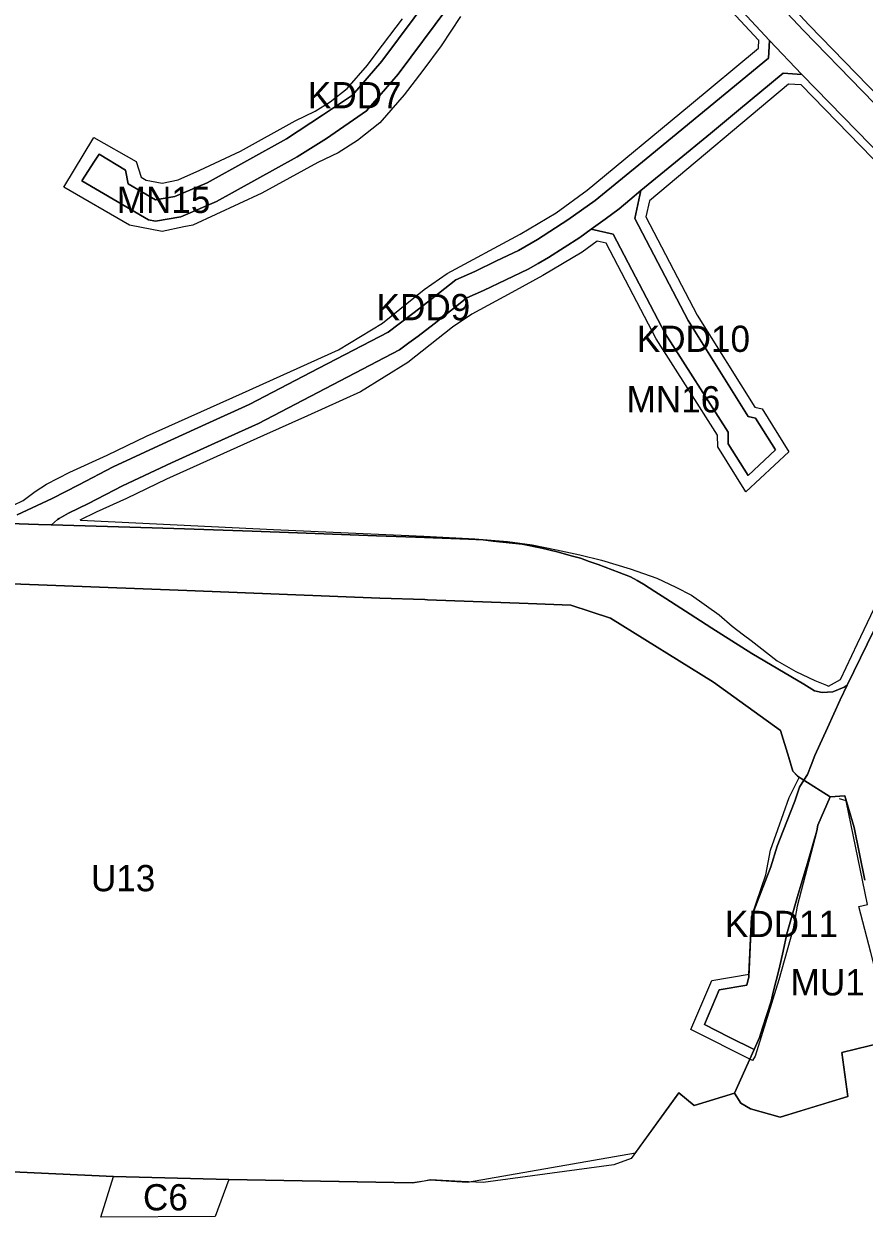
# Model space of a CAD drawing. Extents: x 7428841 to 7433518, y 5545054 to 5546840.
# Drawn here: x 7429933 to 7430252.9, y 5545095 to 5545549.4 of the extents above; entities that cross this region are included whole.
import ezdxf

# ---------------------------------------------------------------- set-up
doc = ezdxf.new("R2010")
doc.units = 0
for name, color, linetype in [('linie_rozgraniczajace', 7, 'Continuous'), ('linie_zabudowy_nieprzekraczalne', 7, 'Continuous'), ('oznaczenia_przeznaczen', 7, 'Continuous')]:
    doc.layers.add(name, color=color, linetype=linetype)

msp = doc.modelspace()

# ---------------------------------------------------------------- linework, layer by layer
at = {"layer": 'linie_rozgraniczajace'}
for points in [[(7430325.58, 5545455.53), (7430312.26, 5545461.16), (7430308.65, 5545461.94), (7430303.75, 5545463), (7430294.58, 5545464.99), (7430289.44, 5545468.09), (7430288.37, 5545469.23), (7430255.3, 5545503.38), (7430229.22, 5545530.19), (7430216.84, 5545543.13), (7430184.02, 5545578.55), (7430149.29, 5545617.28), (7430139.47, 5545621.59), (7430134.46, 5545628.43), (7430133.95, 5545633.65), (7430133.85, 5545634.69), (7430133.44, 5545638.87)], [(7430184.02, 5545578.55), (7430216.84, 5545543.13), (7430216.46, 5545536.4), (7430199.99, 5545522.75), (7430169.9, 5545497.98), (7430150.54, 5545482.12), (7430140.13, 5545474.77), (7430128.5, 5545467.28), (7430121.25, 5545463.06), (7430112.94, 5545459.12), (7430104.62, 5545455.18), (7430097.41, 5545451.95), (7430084.26, 5545441.55), (7430071.73, 5545432.06), (7430045.23, 5545418.26), (7430018.74, 5545404.46), (7430002.3, 5545396.99), (7429985.87, 5545389.51), (7429966.95, 5545380.68), (7429953.87, 5545373.84), (7429943.77, 5545368.69), (7429930.43, 5545362.4)], [(7430211.33, 5545566.73), (7430229.77, 5545546.84), (7430297.16, 5545477.57), (7430299.21, 5545476.27), (7430307.56, 5545474.46), (7430315.9, 5545472.65), (7430319.7, 5545471.04), (7430324.69, 5545468.93), (7430333.47, 5545465.22), (7430342.31, 5545463.53), (7430333.84, 5545457.18), (7430326.2, 5545448.73), (7430325.96, 5545448.44), (7430325.58, 5545455.53)], [(7430359.72, 5545551.27), (7430356.4, 5545538.02), (7430356.1, 5545526.65), (7430336.95, 5545508.06), (7430322.25, 5545491.26), (7430307.56, 5545474.46), (7430299.21, 5545476.27), (7430297.16, 5545477.57), (7430229.77, 5545546.84), (7430211.33, 5545566.73)], [(7430087.86, 5545560.33), (7430069.26, 5545535.23), (7430058.09, 5545522.28), (7430046.7, 5545514.62), (7430032.91, 5545505.64), (7430002.79, 5545488.95), (7429990.43, 5545483.71), (7429983.16, 5545482.4), (7429972.73, 5545488.45), (7429971.67, 5545493.69), (7429961.63, 5545499.76), (7429959.88, 5545497.11), (7429955, 5545489.66), (7429980.42, 5545474.74), (7429983.13, 5545474.27), (7429992.73, 5545476), (7430006.3, 5545481.75), (7430036.98, 5545498.75), (7430048.19, 5545505.79), (7430063.47, 5545516.26), (7430075.51, 5545530.23), (7430094.37, 5545555.69)], [(7430094.37, 5545555.69), (7430075.51, 5545530.23), (7430063.47, 5545516.26), (7430048.19, 5545505.79), (7430036.98, 5545498.75), (7430006.3, 5545481.75), (7429992.73, 5545476), (7429983.13, 5545474.27), (7429980.42, 5545474.74), (7429955, 5545489.66), (7429959.88, 5545497.11), (7429961.63, 5545499.76), (7429971.67, 5545493.69), (7429972.73, 5545488.45), (7429983.16, 5545482.4), (7429990.43, 5545483.71), (7430002.79, 5545488.95), (7430032.91, 5545505.64), (7430046.7, 5545514.62), (7430058.09, 5545522.28), (7430069.26, 5545535.23), (7430087.86, 5545560.33)], [(7429930.43, 5545362.4), (7429943.77, 5545368.69), (7429953.87, 5545373.84), (7429966.95, 5545380.68), (7429985.87, 5545389.51), (7430002.3, 5545396.99), (7430018.74, 5545404.46), (7430045.23, 5545418.26), (7430071.73, 5545432.06), (7430084.26, 5545441.55), (7430097.41, 5545451.95), (7430104.62, 5545455.18), (7430112.94, 5545459.12), (7430121.25, 5545463.06), (7430128.5, 5545467.28), (7430140.13, 5545474.77), (7430150.54, 5545482.12), (7430169.9, 5545497.98), (7430199.99, 5545522.75), (7430216.46, 5545536.4), (7430216.84, 5545543.13), (7430229.22, 5545530.19), (7430222.06, 5545530.65), (7430205.1, 5545516.59), (7430194.35, 5545507.67), (7430181.1, 5545496.81), (7430167.84, 5545485.95), (7430163.72, 5545482.45), (7430159.6, 5545478.95), (7430154.31, 5545475.11), (7430148.92, 5545471.28), (7430144.6, 5545468.13), (7430138.65, 5545464.3), (7430132.69, 5545460.46), (7430128.84, 5545458.22), (7430124.99, 5545455.97), (7430116.48, 5545451.94), (7430107.97, 5545447.92), (7430101.6, 5545445.06), (7430089.2, 5545435.25), (7430083.16, 5545430.54), (7430079.57, 5545427.9), (7430075.97, 5545425.25), (7430022.25, 5545397.27), (7430005.73, 5545389.76), (7429989.22, 5545382.25), (7429970.5, 5545373.51), (7429957.58, 5545366.76), (7429950.04, 5545363.1), (7429946.36, 5545361.08), (7429945.75, 5545360.72), (7429943.55, 5545358.65), (7429943.43, 5545358.65), (7429938.58, 5545358.8), (7429934.73, 5545358.92), (7429920.54, 5545359.36)], [(7430259.11, 5545323.6), (7430246.49, 5545297.57), (7430245.24, 5545296.79), (7430240.91, 5545295.09), (7430236.92, 5545294.77), (7430234, 5545295.48), (7430229.89, 5545297.92), (7430210.16, 5545309.58), (7430202.52, 5545314.44), (7430194.88, 5545319.3), (7430190.6, 5545322.12), (7430177.38, 5545330.58), (7430173.16, 5545333.28), (7430168.95, 5545335.98), (7430166.42, 5545337.42), (7430163.89, 5545338.86), (7430159.63, 5545340.5), (7430151.64, 5545343.53), (7430148.25, 5545344.71), (7430144.86, 5545345.9), (7430141.9, 5545346.72), (7430135.97, 5545348.36), (7430130.17, 5545349.74), (7430122.72, 5545351.23), (7430111.67, 5545352.45), (7430107.83, 5545352.89), (7430102.29, 5545353.23), (7430082.11, 5545353.89), (7430067.3, 5545354.42), (7430037.17, 5545355.64), (7430019.94, 5545356.23), (7429994.1, 5545357.1), (7429981.85, 5545357.5), (7429943.56, 5545358.65), (7429943.55, 5545358.65), (7429945.75, 5545360.72), (7429946.36, 5545361.08), (7429950.04, 5545363.1), (7429957.58, 5545366.76), (7429970.5, 5545373.51), (7429989.22, 5545382.25), (7430005.73, 5545389.76), (7430022.25, 5545397.27), (7430075.97, 5545425.25), (7430079.57, 5545427.9), (7430083.16, 5545430.54), (7430089.2, 5545435.25), (7430101.6, 5545445.06), (7430107.97, 5545447.92), (7430116.48, 5545451.94), (7430124.99, 5545455.97), (7430128.84, 5545458.22), (7430132.69, 5545460.46), (7430138.65, 5545464.3), (7430144.6, 5545468.13), (7430148.92, 5545471.28), (7430157.39, 5545469.39), (7430177.2, 5545431.51), (7430201.09, 5545393.98), (7430201.12, 5545389.51), (7430208.69, 5545377.42), (7430219.12, 5545387.15), (7430211.55, 5545399.24), (7430208.8, 5545399.87), (7430197.34, 5545418.18), (7430185.88, 5545436.49), (7430175.72, 5545455.91), (7430165.56, 5545475.34), (7430167.84, 5545485.95), (7430181.1, 5545496.81), (7430194.35, 5545507.67), (7430205.1, 5545516.59), (7430222.06, 5545530.65), (7430229.22, 5545530.19), (7430255.3, 5545503.38)], [(7429920.54, 5545359.36), (7429934.73, 5545358.92), (7429938.58, 5545358.8), (7429943.43, 5545358.65), (7429943.55, 5545358.65), (7429943.56, 5545358.65), (7429981.85, 5545357.5), (7429994.1, 5545357.1), (7430019.94, 5545356.23), (7430037.17, 5545355.64), (7430067.3, 5545354.42), (7430082.11, 5545353.89), (7430102.29, 5545353.23), (7430107.83, 5545352.89), (7430111.67, 5545352.45), (7430122.72, 5545351.23), (7430130.17, 5545349.74), (7430135.97, 5545348.36), (7430141.9, 5545346.72), (7430144.86, 5545345.9), (7430148.25, 5545344.71), (7430151.64, 5545343.53), (7430159.63, 5545340.5), (7430163.89, 5545338.86), (7430166.42, 5545337.42), (7430168.95, 5545335.98), (7430173.16, 5545333.28), (7430177.38, 5545330.58), (7430190.6, 5545322.12), (7430194.88, 5545319.3), (7430202.52, 5545314.44), (7430210.16, 5545309.58), (7430229.89, 5545297.92), (7430234, 5545295.48), (7430236.92, 5545294.77), (7430240.91, 5545295.09), (7430245.24, 5545296.79), (7430246.49, 5545297.57), (7430243.74, 5545291.97), (7430238.96, 5545281.36), (7430234.18, 5545270.75), (7430232.78, 5545267.15), (7430231.38, 5545263.55), (7430229.95, 5545261.35), (7430227.5, 5545262.9), (7430225.75, 5545264.88), (7430224.18, 5545270.02), (7430221.04, 5545280.34), (7430195.57, 5545298.71), (7430156.29, 5545323.05), (7430141.2, 5545328.03), (7430125.01, 5545328.63), (7430086.64, 5545330.07), (7430085.61, 5545330.21), (7430068.54, 5545330.76), (7429994.98, 5545333.61), (7429895.15, 5545337.47)], [(7429895.15, 5545337.47), (7429994.98, 5545333.61), (7430068.54, 5545330.76), (7430085.61, 5545330.21), (7430086.64, 5545330.07), (7430125.01, 5545328.63), (7430141.2, 5545328.03), (7430156.29, 5545323.05), (7430195.57, 5545298.71), (7430221.04, 5545280.34), (7430224.18, 5545270.02), (7430225.75, 5545264.88), (7430227.5, 5545262.9), (7430229.95, 5545261.35), (7430228.24, 5545258.76), (7430226.53, 5545253.44), (7430222, 5545242.06), (7430219.75, 5545236.25), (7430217.38, 5545228.33), (7430213.66, 5545218.87), (7430209.95, 5545209.41), (7430208.98, 5545186.56), (7430208.22, 5545183.3), (7430197.73, 5545181.56), (7430192.1, 5545168.35), (7430201.55, 5545163.56), (7430211, 5545158.77), (7430203.58, 5545142.22), (7430188.19, 5545137.46), (7430182.29, 5545142.3), (7430164.23, 5545117.25), (7430157.56, 5545114.91), (7430107.8, 5545108.22), (7430099.49, 5545108.6), (7430087.61, 5545109.15), (7430085.34, 5545108.71), (7430080.94, 5545108.08), (7430010.97, 5545109.36), (7429967.17, 5545110.46), (7429766.71, 5545119.71)], [(7430229.95, 5545261.35), (7430231.38, 5545263.55), (7430232.78, 5545267.15), (7430234.18, 5545270.75), (7430238.96, 5545281.36), (7430243.74, 5545291.97), (7430246.49, 5545297.57), (7430259.11, 5545323.6)], [(7430253.11, 5545223.25), (7430249.09, 5545243.33), (7430245.53, 5545255.38), (7430239.96, 5545255.05), (7430229.95, 5545261.35)], [(7430265.18, 5545162.82), (7430244.43, 5545157.62), (7430246.62, 5545140.9), (7430231.3, 5545136.26), (7430220.88, 5545133.1), (7430209.63, 5545136.23), (7430205.95, 5545138.43), (7430203.58, 5545142.22), (7430211, 5545158.77), (7430213.05, 5545163.41), (7430214.23, 5545167.13), (7430217.44, 5545177.23), (7430218.31, 5545180.69), (7430220.54, 5545189.49), (7430222.01, 5545196.28), (7430223.46, 5545202.91), (7430227.51, 5545217.15), (7430231.52, 5545230.7), (7430234.92, 5545242.1), (7430235.21, 5545244.29), (7430239.96, 5545255.05), (7430245.53, 5545255.38), (7430249.09, 5545243.33), (7430253.11, 5545223.25)]]:
    msp.add_lwpolyline(points, dxfattribs=at)
for points in [[(7430148.92, 5545471.28), (7430154.31, 5545475.11), (7430159.6, 5545478.95), (7430163.72, 5545482.45), (7430167.84, 5545485.95), (7430165.56, 5545475.34), (7430175.72, 5545455.91), (7430185.88, 5545436.49), (7430197.34, 5545418.18), (7430208.8, 5545399.87), (7430211.55, 5545399.24), (7430219.12, 5545387.15), (7430208.69, 5545377.42), (7430201.12, 5545389.51), (7430201.09, 5545393.98), (7430177.2, 5545431.51), (7430157.39, 5545469.39)], [(7430192.1, 5545168.35), (7430197.73, 5545181.56), (7430208.22, 5545183.3), (7430208.98, 5545186.56), (7430209.95, 5545209.41), (7430213.66, 5545218.87), (7430217.38, 5545228.33), (7430219.75, 5545236.25), (7430222, 5545242.06), (7430226.53, 5545253.44), (7430228.24, 5545258.76), (7430229.95, 5545261.35), (7430239.96, 5545255.05), (7430235.21, 5545244.29), (7430234.92, 5545242.1), (7430231.52, 5545230.7), (7430227.51, 5545217.15), (7430223.46, 5545202.91), (7430222.01, 5545196.28), (7430220.54, 5545189.49), (7430218.31, 5545180.69), (7430217.44, 5545177.23), (7430214.23, 5545167.13), (7430213.05, 5545163.41), (7430211, 5545158.77), (7430201.55, 5545163.56)], [(7429962.33, 5545094.98), (7429967.17, 5545110.46), (7430010.97, 5545109.36), (7430005.8, 5545095.25)]]:
    msp.add_lwpolyline(points, close=True, dxfattribs=at)
at = {"layer": 'linie_zabudowy_nieprzekraczalne'}
for points in [[(7430167.85, 5545631.23), (7430162.47, 5545626.69), (7430161.79, 5545625.86), (7430166.3, 5545621), (7430195.12, 5545588.64), (7430231.95, 5545548.9), (7430299.06, 5545479.91), (7430300.36, 5545479.08), (7430309.83, 5545477.03)], [(7430212.69, 5545543.2), (7430181.8, 5545576.54), (7430167.38, 5545592.73), (7430147.49, 5545614.79), (7430141.98, 5545616.32)], [(7430099.17, 5545552.22), (7430091.9, 5545541.01), (7430084.85, 5545531.7), (7430077.8, 5545522.39), (7430068.56, 5545511.69), (7430059.97, 5545504.98), (7430052.62, 5545500.34), (7430044.88, 5545496.68), (7430023.55, 5545484.91), (7429997.37, 5545472.74), (7429993.88, 5545472.14), (7429985.64, 5545470.4), (7429973.19, 5545472.8), (7429948.18, 5545487.21), (7429959.57, 5545506.12), (7429975.76, 5545496.99), (7429977.59, 5545491.06), (7429979.58, 5545489.9), (7429985.58, 5545488.74), (7429991.74, 5545489.97), (7429999.97, 5545493.72), (7430015.4, 5545500.97), (7430036.24, 5545512.46), (7430043.93, 5545516.14), (7430049.6, 5545519.72), (7430056.09, 5545524.79), (7430063.8, 5545533.72), (7430067.07, 5545538.1), (7430077.15, 5545551.35)], [(7429916.68, 5545362.36), (7429928.99, 5545366.14), (7429932.75, 5545367.92), (7429937.28, 5545371.39), (7429941.65, 5545374.15), (7429950.43, 5545378.73), (7429964.76, 5545385.17), (7429979.65, 5545392.39), (7430016.19, 5545408.83), (7430052.74, 5545425.27), (7430069.56, 5545435.44), (7430085.37, 5545448.31), (7430094.13, 5545454.32), (7430121.89, 5545469.39), (7430135.65, 5545477.49), (7430147.49, 5545486.06), (7430186.38, 5545518.29), (7430212.67, 5545540.14), (7430212.85, 5545543.36)], [(7430228.97, 5545526.2), (7430224.11, 5545526.47), (7430171.13, 5545482.01)], [(7430301.8, 5545460.36), (7430293.42, 5545462.17), (7430287.64, 5545465.84), (7430228.94, 5545526.18)], [(7430171.13, 5545482.01), (7430169.77, 5545475.91), (7430189.36, 5545438.48), (7430211.31, 5545403.4), (7430214.06, 5545402.77), (7430224.26, 5545386.48), (7430207.87, 5545371.19), (7430197.13, 5545388.35), (7430197.1, 5545392.79), (7430185.78, 5545410.59), (7430173.74, 5545429.5), (7430154.7, 5545465.89), (7430151.3, 5545466.7)], [(7430151.3, 5545466.7), (7430145.55, 5545462.43), (7430130.62, 5545453.58), (7430118.8, 5545447.1), (7430103.51, 5545438.93), (7430096.16, 5545433.89), (7430079.15, 5545420.42), (7430061.19, 5545409.34), (7430040.96, 5545400.19), (7430024.21, 5545392.7), (7429987.24, 5545376.07), (7429972.03, 5545368.71), (7429960.46, 5545363.41), (7429954.35, 5545360.46)], [(7430239.29, 5545297.24), (7430239.29, 5545297.24), (7430243.9, 5545299.69), (7430243.9, 5545299.69), (7430250.35, 5545313.39), (7430268.09, 5545350.71), (7430276.26, 5545368.76), (7430282.12, 5545380.85), (7430286.65, 5545388.92), (7430295.47, 5545407.3), (7430298.99, 5545413.85), (7430303.59, 5545421.71), (7430312.81, 5545436.57), (7430319.95, 5545446.16), (7430323.12, 5545449.81)], [(7429954.49, 5545360.44), (7429967.69, 5545359.81), (7430028.08, 5545356.84), (7430056.41, 5545355.58), (7430085.27, 5545354.26), (7430104.67, 5545353.3), (7430117.08, 5545352.28), (7430126.53, 5545351.02), (7430135.72, 5545349.14), (7430144.64, 5545347.21), (7430152.95, 5545345.13), (7430163.79, 5545341.83), (7430173.91, 5545338.3), (7430181.14, 5545334.91), (7430187.2, 5545331.91), (7430197.7, 5545324.38), (7430202.66, 5545320.06), (7430206.9, 5545316.75), (7430209.89, 5545314.59), (7430219.77, 5545306.89), (7430226.91, 5545302.73), (7430234.13, 5545299.38), (7430238.53, 5545297.54), (7430239.3, 5545297.25)], [(7430141.2, 5545328.03), (7430125.01, 5545328.63), (7430068.54, 5545330.76), (7429994.98, 5545333.61), (7429945.06, 5545335.54), (7429895.15, 5545337.47), (7429871.81, 5545338.38), (7429854.74, 5545339.04), (7429803.03, 5545340.9), (7429751.31, 5545342.75), (7429741.75, 5545333.86), (7429738.51, 5545297), (7429735.28, 5545260.15), (7429733.04, 5545234.55), (7429730.55, 5545206.18)], [(7430195.57, 5545298.71), (7430156.29, 5545323.05), (7430141.2, 5545328.03)], [(7430221.04, 5545280.34), (7430195.57, 5545298.71)], [(7430209.02, 5545187.51), (7430209.95, 5545209.41), (7430215.42, 5545225.36), (7430217.18, 5545234.76), (7430219.97, 5545242.65), (7430224.31, 5545254.78), (7430228.19, 5545262.42), (7430225.75, 5545264.88), (7430223.4, 5545272.61), (7430221.04, 5545280.34)], [(7430245.53, 5545255.37), (7430239.96, 5545255.05), (7430239.96, 5545255.05), (7430237.58, 5545249.65), (7430235.21, 5545244.29), (7430234.92, 5545242.1), (7430227.43, 5545213.38), (7430225.85, 5545204.78), (7430220.46, 5545185.39), (7430211.4, 5545156.25), (7430210.39, 5545154.59)], [(7430263.89, 5545162.52), (7430255.48, 5545195.72), (7430250.93, 5545213.22), (7430254.2, 5545214.02), (7430246.03, 5545253.5), (7430243.52, 5545254.3)], [(7429730.55, 5545206.18), (7429727.14, 5545167.45), (7429732.75, 5545160.67), (7429731.08, 5545153.27), (7429744.53, 5545151.94), (7429742.07, 5545126.13), (7429766.71, 5545119.71), (7429967.17, 5545110.46), (7430010.97, 5545109.36), (7430045.95, 5545108.72), (7430080.94, 5545108.08), (7430087.61, 5545109.15), (7430101.91, 5545108.31), (7430165.88, 5545119.44), (7430182.29, 5545142.3), (7430188.19, 5545137.46), (7430203.58, 5545142.22), (7430205.95, 5545138.43), (7430209.63, 5545136.23), (7430220.88, 5545133.1), (7430233.75, 5545137), (7430246.62, 5545140.9), (7430244.43, 5545157.62), (7430265.18, 5545162.82)], [(7430210.4, 5545154.6), (7430210.4, 5545154.6), (7430186.95, 5545166.47), (7430194.91, 5545185.14), (7430209.13, 5545187.51)]]:
    msp.add_lwpolyline(points, dxfattribs=at)

# ---------------------------------------------------------------- texts
at = {"layer": 'oznaczenia_przeznaczen'}
for s, p in [('KDD7', (7430041.12, 5545517.28)), ('MN15', (7429968.33, 5545477.4)), ('KDD9', (7430067.26, 5545436.55)), ('KDD10', (7430166.34, 5545424.49)), ('MN16', (7430162.43, 5545401.46)), ('U13', (7429958.52, 5545219.09)), ('KDD11', (7430199.89, 5545201.64)), ('MU1', (7430224.89, 5545179.42)), ('C6', (7429978.33, 5545097.54))]:
    msp.add_text(s, height=10, dxfattribs=at).set_placement(p)

doc.saveas('drawing.dxf')
